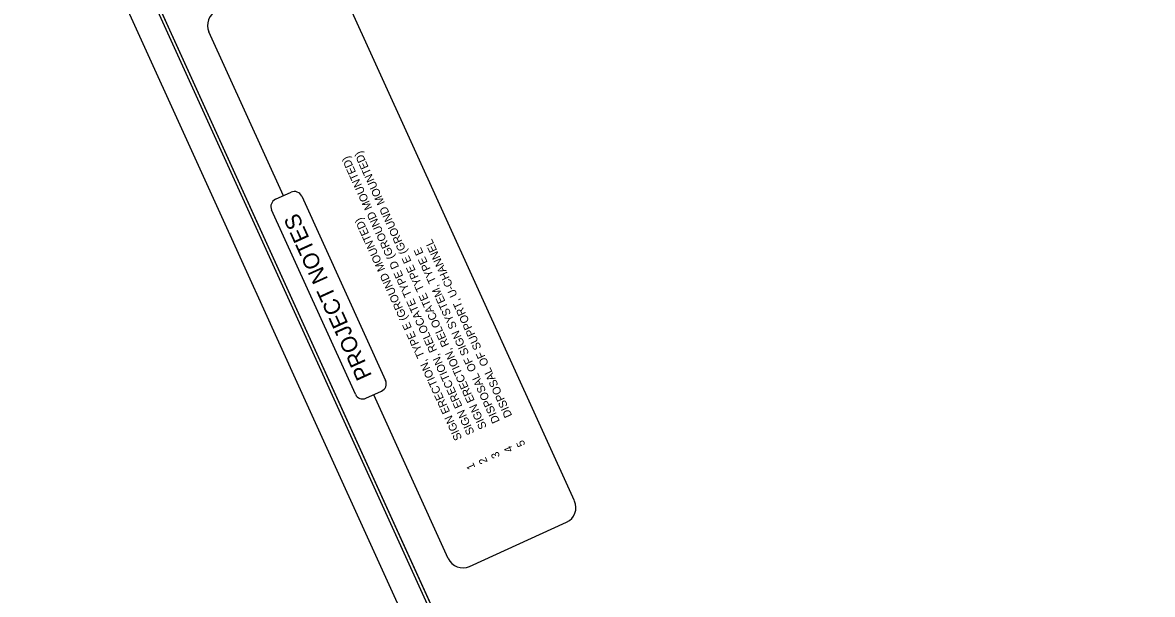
# Model space of a CAD drawing. Extents: x 2096093 to 2099001, y 683546 to 685907.
# Drawn here: x 2097307 to 2098154, y 684843 to 685271 of the extents above; entities that cross this region are included whole.
import ezdxf

# ---------------------------------------------------------------- set-up
doc = ezdxf.new("R2010")
doc.units = 0
for name, color, linetype in [('Default', 7, 'Continuous'), ('Scratch_Level_4', 7, 'Continuous'), ('Sheet Layout Plan Border', 7, 'Continuous'), ('Sheet Plan CELL', 7, 'Continuous'), ('Sheet Plot Border Inside CELL', 7, 'Continuous'), ('Sheet Plot Border Outside CELL', 7, 'Continuous'), ('Sheet Title CELL', 7, 'Continuous')]:
    doc.layers.add(name, color=color, linetype=linetype)

msp = doc.modelspace()

# ---------------------------------------------------------------- linework, layer by layer
at = {"layer": 'Scratch_Level_4'}
msp.add_lwpolyline([(2097576.74, 685472.35), (2098256.77, 685779.32), (2098363.73, 685544.17), (2098430.06, 685574.34), (2098911.14, 684517.12), (2097955.36, 684082.39), (2097417.22, 685265.53), (2097411.63, 685277.84), (2097412.45, 685278.18), (2097621.75, 685373.38)], close=True, dxfattribs=at)
at = {"layer": 'Sheet Layout Plan Border'}
msp.add_lwpolyline([(2097576.74, 685472.35), (2098256.77, 685779.32), (2098363.73, 685544.17), (2098430.06, 685574.34), (2098911.14, 684517.12), (2097955.36, 684082.39), (2097417.22, 685265.53), (2097411.63, 685277.84), (2097412.45, 685278.18), (2097621.75, 685373.38)], close=True, dxfattribs=at)
at = {"layer": 'Sheet Plan CELL'}
msp.add_lwpolyline([(2097334.31, 685447.82), (2097955.36, 684082.39), (2098911.14, 684517.12), (2098290.1, 685882.52)], close=True, dxfattribs=at)
msp.add_lwpolyline([(2097334.31, 685447.82), (2097955.36, 684082.39), (2098911.14, 684517.12), (2098290.1, 685882.52)], close=True, dxfattribs=at)
at = {"layer": 'Sheet Plot Border Inside CELL'}
msp.add_lwpolyline([(2098976.98, 684378.44), (2098287.2, 685894.93), (2097326.88, 685458.15), (2098016.65, 683941.64)], close=True, dxfattribs=at)
msp.add_lwpolyline([(2098976.98, 684378.44), (2098287.2, 685894.93), (2097326.88, 685458.15), (2098016.65, 683941.64)], close=True, dxfattribs=at)
at = {"layer": 'Sheet Plot Border Outside CELL'}
msp.add_lwpolyline([(2099000.57, 684374.89), (2098303.55, 685907.32), (2097306.81, 685453.96), (2098003.83, 683921.53)], close=True, dxfattribs=at)
msp.add_lwpolyline([(2099000.57, 684374.89), (2098303.55, 685907.32), (2097306.81, 685453.96), (2098003.83, 683921.53)], close=True, dxfattribs=at)
at = {"layer": 'Sheet Title CELL'}
for p, q in [((2097720.54, 684912.81), (2097541.15, 685307.21)), ((2097502.27, 685141.45), (2097446.46, 685264.15)), ((2097496.42, 685138.79), (2097508.12, 685144.12)), ((2097516.07, 685141.14), (2097578.88, 685003.04)), ((2097556.25, 684992.75), (2097493.44, 685130.85)), ((2097564.2, 684989.78), (2097575.9, 684995.1)), ((2097625.86, 684869.74), (2097570.05, 684992.44)), ((2097641.75, 684863.79), (2097714.59, 684896.92))]:
    msp.add_line(p, q, dxfattribs=at)
for centre, radius, start, end in [((2097457.39, 685269.12), 12, 114.45798, 204.45798), ((2097510.61, 685138.65), 6, 24.45798, 114.45798), ((2097498.9, 685133.33), 6, 114.45798, 204.45798), ((2097573.42, 685000.56), 6, 294.45798, 24.45798), ((2097561.71, 684995.24), 6, 204.45798, 294.45798), ((2097709.62, 684907.84), 12, 294.45798, 24.45798), ((2097636.78, 684874.71), 12, 204.45798, 294.45798)]:
    msp.add_arc(centre, radius, start, end, dxfattribs=at)

# ---------------------------------------------------------------- texts
at = {"layer": 'Default'}
for s, height, p in [('SIGN ERECTION, RELOCATE TYPE E (GROUND MOUNTED)', 6, (2097654.91, 684968.16)), ('SIGN ERECTION, RELOCATE TYPE D (GROUND MOUNTED)', 6, (2097645.66, 684963.95)), ('PROJECT NOTES', 12, (2097568.87, 685006.67)), ('SIGN ERECTION, TYPE E (GROUND MOUNTED)', 6, (2097636.4, 684959.74)), ('DISPOSAL OF SUPPORT, U-CHANNEL', 6, (2097673.92, 684976.81)), ('DISPOSAL OF SIGN SYSTEM, TYPE E', 6, (2097664.67, 684972.6)), ('4', 6, (2097674.61, 684950.75)), ('5', 6, (2097683.86, 684954.96)), ('2', 6, (2097655.6, 684942.1)), ('3', 6, (2097664.85, 684946.31)), ('1', 6, (2097646.34, 684937.89))]:
    msp.add_text(s, height=height, rotation=114.45798, dxfattribs=at).set_placement(p)

doc.saveas('drawing.dxf')
